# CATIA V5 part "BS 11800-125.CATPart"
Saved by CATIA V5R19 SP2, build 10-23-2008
Part number: BS 11800-125
Bounding box of the stored display mesh (mm): x -74.81 to 74.81, y -74.81 to 74.81, z 0 to 328
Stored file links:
  C:\Users\Bora\Desktop\3D Katı model\BS serisi\BS 11800\BS 11800-125.CATPart
  C:\Program Files\Dassault Systemes\B19\intel_a\reffiles\standard\MetricThickPitch.txt
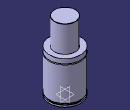
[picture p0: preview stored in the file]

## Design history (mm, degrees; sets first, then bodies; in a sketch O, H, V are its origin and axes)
Body1 (main body)
  Sketch1 on yz-plane, origin (0, 0, 0), H (0, 1, 0), V (0, 0, 1)
    point P1 (75, 180)
    point P2 (75, 175)
    point P5 (50, 327)
    point P7 (50, 327)
    point P12 (75, 175)
    point P13 (75, 180)
    arc A1 centre (75, 177.5) radius 2.5 from (75, 180) to (75, 175) ccw
    line L1 (75, 0) -> (75, 8)
    line L2 (50, 327) -> (50, 202)
    arc A2 centre (49, 327) radius 1 from (50, 327) to (49, 328) ccw
    line L3 (71, 15) -> (71, 8)
    line L4 (75, 15) -> (75, 175)
    line L5 (75, 180) -> (75, 202)
    line L6 (49, 328) -> (0, 328)
    point P15 (0, 328)
    line L7 (50, 202) -> (75, 202)
    line L8 (0, 0) -> (75, 0)
    line L9 (71, 15) -> (75, 15)
    line L10 (71, 8) -> (75, 8)
    coincidence: P15 V, P1 P13, P2 P12, P5 P7
    tangency: L6 A2
    horizontal: L7 H, L8 H, L9 H, L10 H
  Shaft1: profile Sketch1, axis Sketch1.V, angle 360
  Sketch2 on face of Shaft1 from Sketch1.L8, origin (0, 0, 0), H (1, 0, 0), V (0, -1, 0)
    point P1 (50, 0)
    distance P1 V = 50
  Hole1: placed by Sketch2, at (50, 0, 0) direction (0, 0, 1), diameter 8.376, depth 12, threaded "M10", thread diameter 10, thread depth 12, pitch 1.5
  CircPattern1: of Hole1, instances 4, angular step 90, axis from xy-plane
